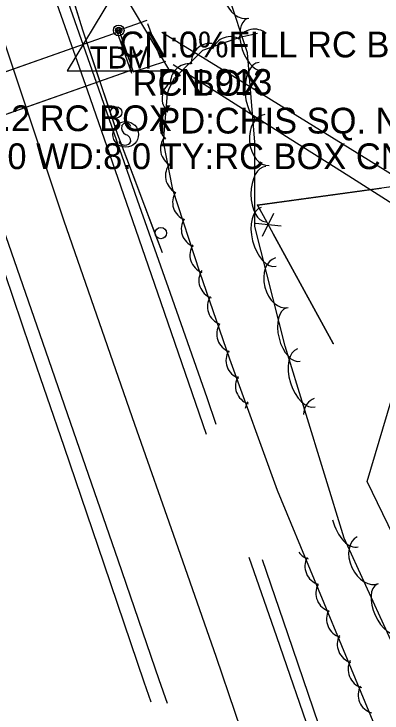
# Model space of a CAD drawing. Extents: x 954793 to 988390, y 1867850 to 1924428.
# Drawn here: x 961063.7 to 961135.1, y 1907670.9 to 1907806.5 of the extents above; entities that cross this region are included whole.
import ezdxf

# ---------------------------------------------------------------- set-up
doc = ezdxf.new("R2010")
doc.units = 0
for name, color, linetype in [('S_CROSS_DRAIN', 7, 'Continuous'), ('S_CROSS_DRAIN_ANNOT', 7, 'Continuous'), ('S_DRG_PT_SYM', 7, 'Continuous'), ('S_EDGE_CONCRETE', 7, 'Continuous'), ('S_EDGE_PAVEMENT', 7, 'Continuous'), ('S_FENCE', 7, 'Continuous'), ('S_GUARDRAIL', 7, 'Continuous'), ('S_HEADWALL', 7, 'Continuous'), ('S_MSC_PT_SYM', 7, 'Continuous'), ('S_PAVEMENT_CROWN', 7, 'Continuous'), ('S_PRIMARY_CTL', 7, 'Continuous'), ('S_PRIMARY_CTL_ANNOT', 7, 'Continuous'), ('S_SHOULDER', 7, 'Continuous'), ('S_SIGN', 7, 'Continuous'), ('S_STREAM', 7, 'Continuous'), ('S_TREE', 7, 'Continuous')]:
    doc.layers.add(name, color=color, linetype=linetype)

msp = doc.modelspace()

# ---------------------------------------------------------------- linework, layer by layer
at = {"layer": 'S_CROSS_DRAIN'}
for p, q in [((961043.4, 1907788.78), (961084.12, 1907803.09)), ((961084.12, 1907803.09), (961086.69, 1907795.65)), ((961086.69, 1907795.65), (961046.04, 1907781.41))]:
    msp.add_line(p, q, dxfattribs=at)
msp.add_lwpolyline([(961046.04, 1907781.41), (961043.4, 1907788.78), (961084.12, 1907803.09), (961086.69, 1907795.65), (961046.04, 1907781.41)], dxfattribs=at)
msp.add_lwpolyline([(961046.04, 1907781.41), (961043.4, 1907788.78), (961084.12, 1907803.09), (961086.69, 1907795.65), (961046.04, 1907781.41)], dxfattribs=at)
at = {"layer": 'S_DRG_PT_SYM'}
for points in [[(961084.12, 1907803.09), (961084.12, 1907803.14), (961084.12, 1907803.09), (961084.07, 1907803.09), (961084.12, 1907803.09), (961084.12, 1907803.04), (961084.12, 1907803.09), (961084.17, 1907803.09)], [(961084.12, 1907803.09), (961084.17, 1907803.11), (961084.12, 1907803.09), (961084.11, 1907803.14), (961084.12, 1907803.09), (961084.07, 1907803.07), (961084.12, 1907803.09), (961084.14, 1907803.04)], [(961084.12, 1907803.09), (961084.12, 1907803.14), (961084.12, 1907803.09), (961084.07, 1907803.09), (961084.12, 1907803.09), (961084.12, 1907803.04), (961084.12, 1907803.09), (961084.17, 1907803.09)], [(961084.12, 1907803.09), (961084.17, 1907803.11), (961084.12, 1907803.09), (961084.11, 1907803.14), (961084.12, 1907803.09), (961084.07, 1907803.07), (961084.12, 1907803.09), (961084.14, 1907803.04)], [(961086.69, 1907795.65), (961086.69, 1907795.7), (961086.69, 1907795.65), (961086.64, 1907795.65), (961086.69, 1907795.65), (961086.69, 1907795.6), (961086.69, 1907795.65), (961086.74, 1907795.65)], [(961086.69, 1907795.65), (961086.69, 1907795.7), (961086.69, 1907795.65), (961086.64, 1907795.65), (961086.69, 1907795.65), (961086.69, 1907795.6), (961086.69, 1907795.65), (961086.74, 1907795.65)], [(961086.69, 1907795.65), (961086.71, 1907795.61), (961086.69, 1907795.65), (961086.74, 1907795.67), (961086.69, 1907795.65), (961086.68, 1907795.7), (961086.69, 1907795.65), (961086.65, 1907795.64)], [(961086.69, 1907795.65), (961086.71, 1907795.61), (961086.69, 1907795.65), (961086.74, 1907795.67), (961086.69, 1907795.65), (961086.68, 1907795.7), (961086.69, 1907795.65), (961086.65, 1907795.64)]]:
    msp.add_lwpolyline(points, close=True, dxfattribs=at)
for points in [[(961084.12, 1907803.09), (961084.12, 1907803.14), (961084.12, 1907803.09), (961084.07, 1907803.09), (961084.12, 1907803.09), (961084.12, 1907803.04), (961084.12, 1907803.09), (961084.17, 1907803.09)], [(961086.69, 1907795.65), (961086.69, 1907795.7), (961086.69, 1907795.65), (961086.64, 1907795.65), (961086.69, 1907795.65), (961086.69, 1907795.6), (961086.69, 1907795.65), (961086.74, 1907795.65)]]:
    msp.add_lwpolyline(points, dxfattribs=at)
at = {"layer": 'S_EDGE_CONCRETE'}
msp.add_lwpolyline([(961089.6, 1907804.68), (961092.06, 1907797.98)], dxfattribs=at)
at = {"layer": 'S_EDGE_PAVEMENT'}
for points in [[(961101.03, 1907724.95), (961098.95, 1907730.96), (961092.24, 1907750.45), (961085.52, 1907769.95), (961077.97, 1907791.51), (961070.42, 1907813.07), (961064, 1907831.48), (961057.58, 1907849.89), (961050.38, 1907870.36), (961043.18, 1907890.83), (961036.4, 1907910), (961029.63, 1907929.18), (961022.42, 1907949.87), (961015.21, 1907970.56), (961009.38, 1907987.28), (961003.56, 1908004), (960996.94, 1908023.02), (960990.87, 1908040.47)], [(961093.44, 1907672.76), (961091.85, 1907677.33), (961083.85, 1907700.53), (961075.84, 1907723.73), (961069.24, 1907742.76), (961062.63, 1907761.78), (961055.09, 1907783.45), (961047.55, 1907805.13), (961041.02, 1907823.69), (961034.5, 1907842.26), (961027.28, 1907862.75), (961020.06, 1907883.25), (961013.34, 1907902.44), (961006.61, 1907921.64), (960999.45, 1907942.16), (960995.59, 1907953.21)], [(961121.69, 1907665.23), (961114.64, 1907685.71), (961109.33, 1907701.05)]]:
    msp.add_lwpolyline(points, dxfattribs=at)
at = {"layer": 'S_FENCE'}
for p, q in [((961154.36, 1907775.34), (961110.9, 1907769.45)), ((961110.9, 1907769.45), (961125.63, 1907742.6)), ((961111.89, 1907763.38), (961114.1, 1907767.86)), ((961115.48, 1907765.35), (961110.51, 1907765.89))]:
    msp.add_line(p, q, dxfattribs=at)
for points in [[(961206.21, 1907779.64), (961154.36, 1907775.34), (961110.9, 1907769.45), (961125.63, 1907742.6)], [(961206.21, 1907779.64), (961154.36, 1907775.34), (961110.9, 1907769.45), (961125.63, 1907742.6)], [(961110.9, 1907769.45), (961134.94, 1907772.7)], [(961112.31, 1907766.88), (961110.9, 1907769.45)], [(961125.63, 1907742.6), (961113.96, 1907763.87)]]:
    msp.add_lwpolyline(points, dxfattribs=at)
at = {"layer": 'S_GUARDRAIL'}
for points in [[(961070.97, 1907822.77), (961076.97, 1907803.46), (961083.77, 1907783.12), (961092.4, 1907760.27)], [(961074.68, 1907810.83), (961076.97, 1907803.46), (961082.45, 1907787.07)], [(961082.45, 1907787.07), (961083.77, 1907783.12), (961086.71, 1907775.32)], [(961086.71, 1907775.32), (961091.13, 1907763.62)], [(961091.13, 1907763.62), (961092.4, 1907760.27)]]:
    msp.add_lwpolyline(points, dxfattribs=at)
for centre in [(961083.49, 1907787.41), (961092.16, 1907764.01)]:
    msp.add_circle(centre, 1.1, dxfattribs=at)
at = {"layer": 'S_HEADWALL'}
for points in [[(961083.82, 1907803.3), (961089.53, 1907805.3)], [(961086.51, 1907794.94), (961083.56, 1907803.44)], [(961093.07, 1907797.28), (961086.74, 1907795.19)]]:
    msp.add_lwpolyline(points, dxfattribs=at)
at = {"layer": 'S_MSC_PT_SYM'}
for points in [[(961110.9, 1907769.45), (961110.9, 1907769.5), (961110.9, 1907769.45), (961110.85, 1907769.45), (961110.9, 1907769.45), (961110.9, 1907769.4), (961110.9, 1907769.45), (961110.95, 1907769.45)], [(961125.63, 1907742.6), (961125.63, 1907742.65), (961125.63, 1907742.6), (961125.58, 1907742.6), (961125.63, 1907742.6), (961125.63, 1907742.55), (961125.63, 1907742.6), (961125.68, 1907742.6)]]:
    msp.add_lwpolyline(points, dxfattribs=at)
for points in [[(961110.9, 1907769.45), (961110.94, 1907769.47), (961110.9, 1907769.45), (961110.87, 1907769.49), (961110.9, 1907769.45), (961110.85, 1907769.42), (961110.9, 1907769.45), (961110.92, 1907769.4)], [(961110.9, 1907769.45), (961110.94, 1907769.47), (961110.9, 1907769.45), (961110.87, 1907769.49), (961110.9, 1907769.45), (961110.85, 1907769.42), (961110.9, 1907769.45), (961110.92, 1907769.4)], [(961125.63, 1907742.6), (961125.67, 1907742.62), (961125.63, 1907742.6), (961125.61, 1907742.64), (961125.63, 1907742.6), (961125.59, 1907742.57), (961125.63, 1907742.6), (961125.65, 1907742.55)], [(961125.63, 1907742.6), (961125.67, 1907742.62), (961125.63, 1907742.6), (961125.61, 1907742.64), (961125.63, 1907742.6), (961125.59, 1907742.57), (961125.63, 1907742.6), (961125.65, 1907742.55)]]:
    msp.add_lwpolyline(points, close=True, dxfattribs=at)
at = {"layer": 'S_PAVEMENT_CROWN'}
msp.add_lwpolyline([(961110.09, 1907660.76), (961102.93, 1907681.67), (961095.04, 1907704.26), (961087.14, 1907726.85), (961080.28, 1907746.59), (961073.41, 1907766.32), (961066.26, 1907787.67), (961059.1, 1907809.02), (961052.49, 1907827.52), (961045.88, 1907846.02), (961038.87, 1907866.42), (961031.86, 1907886.81), (961025.07, 1907906.18), (961018.28, 1907925.55), (961011, 1907946.17), (961003.73, 1907966.78), (960997.97, 1907983.11), (960992.22, 1907999.43), (960985.59, 1908018.85), (960978.97, 1908038.26), (960972.25, 1908058.26), (960965.52, 1908078.27), (960958.29, 1908100.22)], dxfattribs=at)
at = {"layer": 'S_PRIMARY_CTL'}
for p, q in [((961083.98, 1907812.02), (961073.95, 1907795.51)), ((961083.98, 1907812.02), (961093.81, 1907795.51)), ((961073.95, 1907795.51), (961093.81, 1907795.51))]:
    msp.add_line(p, q, dxfattribs=at)
for radius in [1.04, 0.609, 0.344]:
    msp.add_circle((961083.98, 1907803.32), radius, dxfattribs=at)
at = {"layer": 'S_SHOULDER'}
for points in [[(961102.9, 1907726.86), (961101.13, 1907732.03), (961094.39, 1907751.2), (961087.65, 1907770.38), (961080.11, 1907791.95), (961072.57, 1907813.51), (961066.16, 1907832.07), (961059.75, 1907850.62), (961052.41, 1907870.94), (961045.06, 1907891.25), (961038.41, 1907910.56), (961031.75, 1907929.88), (961024.53, 1907950.54), (961017.31, 1907971.19), (961011.44, 1907987.98), (961005.58, 1908004.76), (960999.17, 1908023.68), (960993.5, 1908040.43)], [(961090.28, 1907673.03), (961088.95, 1907676.9), (961081.17, 1907699.77), (961073.39, 1907722.64), (961066.82, 1907741.75), (961060.24, 1907760.86), (961052.8, 1907782.61), (961045.37, 1907804.35), (961038.65, 1907822.9), (961031.93, 1907841.44), (961024.64, 1907861.7), (961017.35, 1907881.96), (961010.5, 1907901.32), (961003.65, 1907920.68), (960996.57, 1907941.18), (960993.13, 1907951.13)], [(961123.79, 1907665.76), (961116.8, 1907686.26), (961111.88, 1907700.64)]]:
    msp.add_lwpolyline(points, dxfattribs=at)
at = {"layer": 'S_SIGN'}
msp.add_circle((961085.35, 1907783.15), 2.49, dxfattribs=at)
for centre, radius, start, end in [((961086.03, 1907784.47), 1.5, 167.1196, 241.9813), ((961085.42, 1907784.41), 0.95, 16.5258, 156.8957), ((961084.93, 1907781.8), 1.4, 358.6529, 73.7063), ((961085.19, 1907782.32), 1.28, 204.641, 335.359)]:
    msp.add_arc(centre, radius, start, end, dxfattribs=at)
at = {"layer": 'S_STREAM'}
for points in [[(961154.07, 1907744.11), (961145.94, 1907747.6), (961144.02, 1907770.96), (961131.11, 1907778.96), (961118.2, 1907786.95), (961105.29, 1907794.94), (961092.38, 1907802.93)], [(961265.09, 1907498.65), (961253.16, 1907514.11), (961241.23, 1907529.58), (961229.3, 1907545.05), (961217.37, 1907560.52), (961208.28, 1907580.97), (961196.38, 1907599.97), (961184.48, 1907618.98), (961172.59, 1907637.98), (961160.69, 1907656.98), (961153.56, 1907671.7), (961146.44, 1907686.41), (961139.31, 1907701.13), (961132.19, 1907715.85), (961136.85, 1907731.48), (961141.52, 1907747.11), (961140.01, 1907767.82), (961128.64, 1907775.03), (961117.27, 1907782.24), (961105.89, 1907789.46), (961094.52, 1907796.67)]]:
    msp.add_lwpolyline(points, dxfattribs=at)
at = {"layer": 'S_TREE'}
for points in [[(961152.21, 1907657.07), (961140.34, 1907677.29), (961127.75, 1907704.8), (961116.28, 1907742.07), (961110.4, 1907765.26), (961110.4, 1907781.63), (961108.97, 1907799), (961101.57, 1907821.29), (961093.61, 1907837.71), (961092.33, 1907841.26)], [(961234.45, 1907493.11), (961220.82, 1907487.41), (961211.96, 1907480.21), (961204.39, 1907477.36), (961200.52, 1907477.43), (961198.03, 1907483.1), (961163.53, 1907586.87), (961136.33, 1907662.09), (961114.79, 1907714.08), (961105.57, 1907739.52), (961099.75, 1907756.41), (961094.5, 1907772.46), (961092.67, 1907781.69), (961093.48, 1907791.07), (961093.78, 1907792.05), (961094.81, 1907794.08), (961100.29, 1907799.49), (961107.48, 1907802.03), (961109.83, 1907802.53), (961110.9, 1907802.81)]]:
    msp.add_lwpolyline(points, dxfattribs=at)
for centre, start, end in [((961110.34, 1907799.92), 51.0946, 152.6915), ((961105.64, 1907798.48), 58.7152, 160.3121), ((961101.71, 1907797.16), 83.8357, 185.4326), ((961097.67, 1907793.21), 83.8357, 185.4326), ((961096.03, 1907790.13), 124.283, 225.88), ((961095.62, 1907784.84), 124.283, 225.88), ((961095.72, 1907780.37), 140.4322, 242.0291), ((961096.69, 1907775.12), 140.4322, 242.0291), ((961098.08, 1907769.99), 147.2869, 248.8838), ((961099.76, 1907764.81), 147.2869, 248.8838), ((961101.44, 1907759.78), 147.2869, 248.8838), ((961103.18, 1907754.84), 148.2323, 249.8292), ((961104.85, 1907749.77), 148.2323, 249.8292), ((961106.66, 1907744.42), 148.2323, 249.8292), ((961108.44, 1907739.32), 149.1065, 250.7034), ((961110.28, 1907734.35), 149.1065, 250.7034), ((961112.14, 1907729.41), 149.1065, 170.4861), ((961121.79, 1907704.32), 217.8798, 253.3043), ((961123.76, 1907699.36), 151.7074, 253.3043), ((961125.89, 1907694.13), 151.7074, 253.3043), ((961127.97, 1907689.1), 151.7074, 253.3043), ((961130.04, 1907684.22), 151.7074, 253.3043), ((961132.13, 1907679.36), 151.7074, 253.3043), ((961134.1, 1907674.41), 151.7074, 253.3043)]:
    msp.add_arc(centre, 3.64, start, end, dxfattribs=at)
for centre, major_axis, ratio, start_param, end_param in [((961107.69, 1907810.42), (1.56, -4.7), 0.685311, 3.141593, 6.283185), ((961110.69, 1907800.56), (1.69, -5.07), 0.540699, 3.141593, 6.283185), ((961111.73, 1907791.27), (0.48, -5.85), 0.55008, 3.141593, 6.283185), ((961112.75, 1907782.06), (0.41, -4.94), 0.685311, 3.141593, 6.283185), ((961112.52, 1907771.56), (0, -5.35), 0.540699, 3.141593, 6.283185), ((961113.09, 1907763.29), (1.44, -5.69), 0.55008, 3.141593, 6.283185), ((961115.62, 1907754.38), (1.22, -4.8), 0.685311, 3.141593, 6.283185), ((961117.89, 1907744.33), (1.31, -5.18), 0.540699, 3.141593, 6.283185), ((961120.39, 1907735.93), (1.73, -5.61), 0.55008, 3.141593, 6.283185), ((961123.36, 1907727.16), (1.46, -4.74), 0.685311, 3.141593, 4.159612), ((961128.75, 1907708.76), (1.73, -5.61), 0.55008, 4.607481, 6.283185), ((961132.32, 1907700.55), (2.06, -4.51), 0.685311, 3.141593, 6.283185), ((961136.37, 1907691.07), (2.22, -4.86), 0.540699, 3.141593, 6.283185)]:
    msp.add_ellipse(centre, major_axis=major_axis, ratio=ratio, start_param=start_param, end_param=end_param, dxfattribs=at)

# ---------------------------------------------------------------- texts
at = {"layer": 'S_CROSS_DRAIN_ANNOT'}
for s, p in [('CN:0%FILL RC BOX', (961084.12, 1907798.09)), ('RC BOX', (961086.69, 1907790.65)), ('LN:43.2 RC BOX', (961043.4, 1907783.78)), ('HT:4.0 WD:8.0 TY:RC BOX CN:0%FI', (961046.04, 1907776.41))]:
    msp.add_text(s, height=5, dxfattribs=at).set_placement(p)
at = {"layer": 'S_PRIMARY_CTL'}
msp.add_text('TBM', height=4.287, rotation=360, dxfattribs=at).set_placement((961078.33, 1907795.93))
at = {"layer": 'S_PRIMARY_CTL_ANNOT'}
for s, p in [('PN:913', (961091.48, 1907790.82)), ('PD:CHIS SQ. N.END HW', (961091.48, 1907783.32))]:
    msp.add_text(s, height=5, dxfattribs=at).set_placement(p)

doc.saveas('drawing.dxf')
